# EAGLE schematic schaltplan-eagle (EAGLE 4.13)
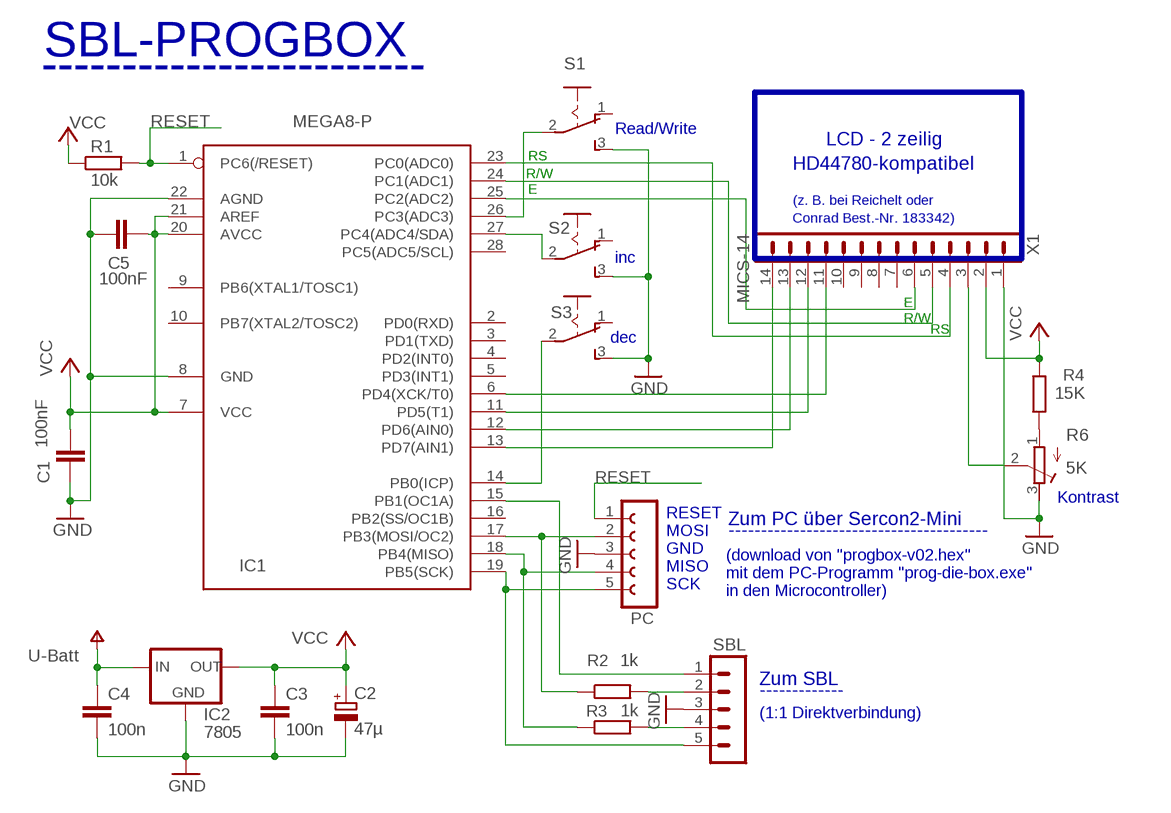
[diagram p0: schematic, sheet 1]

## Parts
C1  100nF  C-EUC0805  [C0805]
C2  47µ  CPOL-EUB/3528-21R  [B/3528-21R]
C3  100n  C-EUC0805  [C0805]
C4  100n  C-EUC0805  [C0805]
C5  100nF  C-EUC0805  [C0805]
IC1  MEGA8-P  [DIL28-3]
IC2  7805  78LXX  [78LXX]
PC  FE05-1  [FE05-1]
R1  10k  R-EU_R0805  [R0805]
R2  1k  R-EU_R0805  [R0805]
R3  1k  R-EU_R0805  [R0805]
R4  15K  R-EU_R0805  [R0805]
R6  5K  R-TRIMM3296P  [RTRIM3296P]
S1  255SB  [255SB]
S2  255SB  [255SB]
S3  255SB  [255SB]
SBL  MA05-1  [MA05-1]
X1  MICS-14  [MICS-14]

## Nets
GND: C1.2 C2.- C3.2 C4.2 C5.2 IC1.8(GND) IC1.22(AGND) IC2.GND PC.3 R6.3(A) S1.3(S) S2.3(S) S3.3(S) SBL.3 X1.1
N$1: R2.2 SBL.2
N$2: IC1.13(PD7(AIN1)) X1.14
N$3: IC1.12(PD6(AIN0)) X1.13
N$4: IC1.11(PD5(T1)) X1.12
N$5: IC1.6(PD4(XCK/T0)) X1.11
N$6: IC1.25(PC2(ADC2)) X1.6
N$7: IC1.23(PC0(ADC0)) X1.4
N$8: IC1.14(PB0(ICP)) S3.2(P)
N$9: IC1.19(PB5(SCK)) PC.5 SBL.5
N$10: IC1.18(PB4(MISO)) PC.4 R3.1
N$11: IC1.17(PB3(MOSI/OC2)) PC.2 R2.1
N$12: R3.2 SBL.4
N$13: IC1.15(PB1(OC1A)) SBL.1
N$14: R6.2(S) X1.3
N$16: R4.1 R6.1(E)
N$17: IC1.27(PC4(ADC4/SDA)) S2.2(P)
N$18: IC1.26(PC3(ADC3)) S1.2(P)
N$19: IC1.24(PC1(ADC1)) X1.5
RESET: IC1.1(PC6(/RESET)) PC.1 R1.2
V+: C4.1 IC2.IN ; supply symbol labelled U-Batt
VCC: C1.1 C2.+ C3.1 C5.1 IC1.7(VCC) IC1.20(AVCC) IC1.21(AREF) IC2.OUT R1.1 R4.2 X1.2
Unconnected: IC1.2(PD0(RXD)) IC1.3(PD1(TXD)) IC1.4(PD2(INT0)) IC1.5(PD3(INT1)) IC1.9(PB6(XTAL1/TOSC1)) IC1.10(PB7(XTAL2/TOSC2)) IC1.16(PB2(SS/OC1B)) IC1.28(PC5(ADC5/SCL)) S1.1(O) S2.1(O) S3.1(O) X1.7 X1.8 X1.9 X1.10

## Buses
B$1

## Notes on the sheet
- SBL-PROGBOX
- ------------------------
- Read/Write
- LCD - 2 zeilig
- RS
- HD44780-kompatibel
- R/W
- E
- (z. B. bei Reichelt oder
- Conrad Best.-Nr. 183342)
- inc
- E
- R/W
- RS
- dec
- Kontrast
- RESET
- Zum PC über Sercon2-Mini
- MOSI | ----------------------------------------
- GND
- (download von "progbox-v02.hex"
- MISO
- mit dem PC-Programm "prog-die-box.exe"
- SCK
- in den Microcontroller)
- Zum SBL
- -------------
- (1:1 Direktverbindung)

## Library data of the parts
C1 C3-C5 = rcl:C-EU: CAPACITOR, European symbol
C2 = rcl:CPOL-EU: POLARIZED CAPACITOR, European symbol
IC1 = avr:MEGA8-P: MICROCONTROLLER 8 Kbytes FLASH 1 kbytes SRAM 512 bytes EEPROM USART 4-channel 10 bit ADC 2-channel 8 bit ADC
IC2 = v-reg:78LXX: VOLTAGE REGULATOR
PC = con-lsta:FE05-1: FEMALE HEADER
R1-R4 = rcl:R-EU_: RESISTOR, European symbol
R6 = rcl:R-TRIMM: Trimm resistor
S1-S3 = switch:255SB: SLIDING SWITCH distributor Buerklin, 11G810
SBL = con-lstb:MA05-1: PIN HEADER
X1 = con-lumberg:MICS-14: CONNECTOR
